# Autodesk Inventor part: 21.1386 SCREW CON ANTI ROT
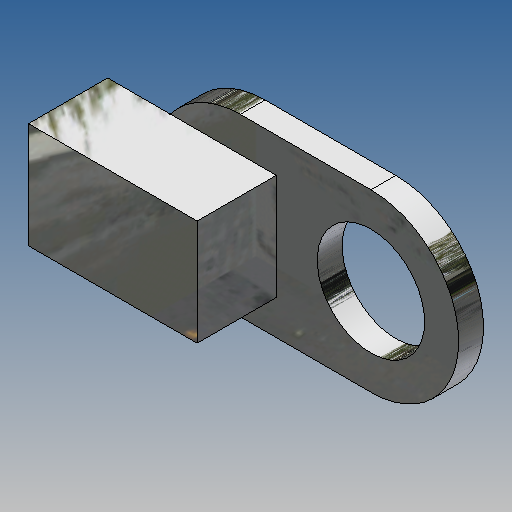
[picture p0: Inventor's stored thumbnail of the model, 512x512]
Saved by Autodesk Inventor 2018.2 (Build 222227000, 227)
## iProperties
Created: 2006-12
Part Number: 21.1386 SCREW CON ANTI ROT
Document SubType Name: Modeling
Designer: Andy Moles
Material: Aluminum-6061
Mass: 2.83425 g
Surface Area: 9.25543 cm^2
Volume: 1.04972 cm^3
Density: 2.7 g/cm^3
Appearance: Anodized - White
Author: Andy Moles
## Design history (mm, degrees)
sketch "Sketch1"
  geometry: L1 (-19.518, 6.726)-(-9.535, 6.726); L2 (-19.518, -6.66)-(-9.535, -6.66); C1 r 4.1 at (-9.535, 0.033); A1 r 6.693 centre (-9.535, 0.033) between (-9.535, -6.66) and (-9.535, 6.726); A2 r 6.693 centre (-19.518, 0.033) between (-19.518, 6.726) and (-19.518, -6.66)
  constraints: 4 end point, 4 point on circle, 3 centre point, 2 tangent, 1 coincident, 1 horizontal, 1 horizontal alignment, 1 parallel
  dimensions: "d0" = 8.2 diameter of C1; "d1" = 13.3858 diameter of A1; "d2" = 13.3858 diameter of A2 (= d1); "d3" = 23.368 dimension on A1 A2
extrude "Extrusion1" new body sketch "Sketch1" distance "d4" = 1.9; taper "d5" = 0 deg
sketch "Sketch2"
  geometry: L1 (-16.76, 4.071)-(-29.637, 4.071); L2 (-29.637, 4.071)-(-29.637, -4.006); L3 (-29.637, -4.006)-(-16.76, -4.006); L4 (-16.76, -4.006)-(-16.76, 4.071); L5 (-16.76, -4.006)-(-29.637, 4.071); C1 r 4.1 at (-9.535, 0.033) reference; A1 r 6.693 centre (-19.518, 0.033) between (-19.518, 6.726) and (-19.518, -6.66) reference; 2 further points
  constraints: 10 end point, 2 parallel, 1 horizontal, 1 horizontal alignment, 1 midpoint, 1 perpendicular
  dimensions: "d6" = 12.8778 distance of L1.start L1.end; "d7" = 8.0772 distance of L1.end L2.end; "d8" = 16.002 distance edge to line of C1 L2
extrude "Extrusion2" join sketch "Sketch2" distance "d9" = 6.0452; taper "d10" = 0 deg
body "Solid1"
